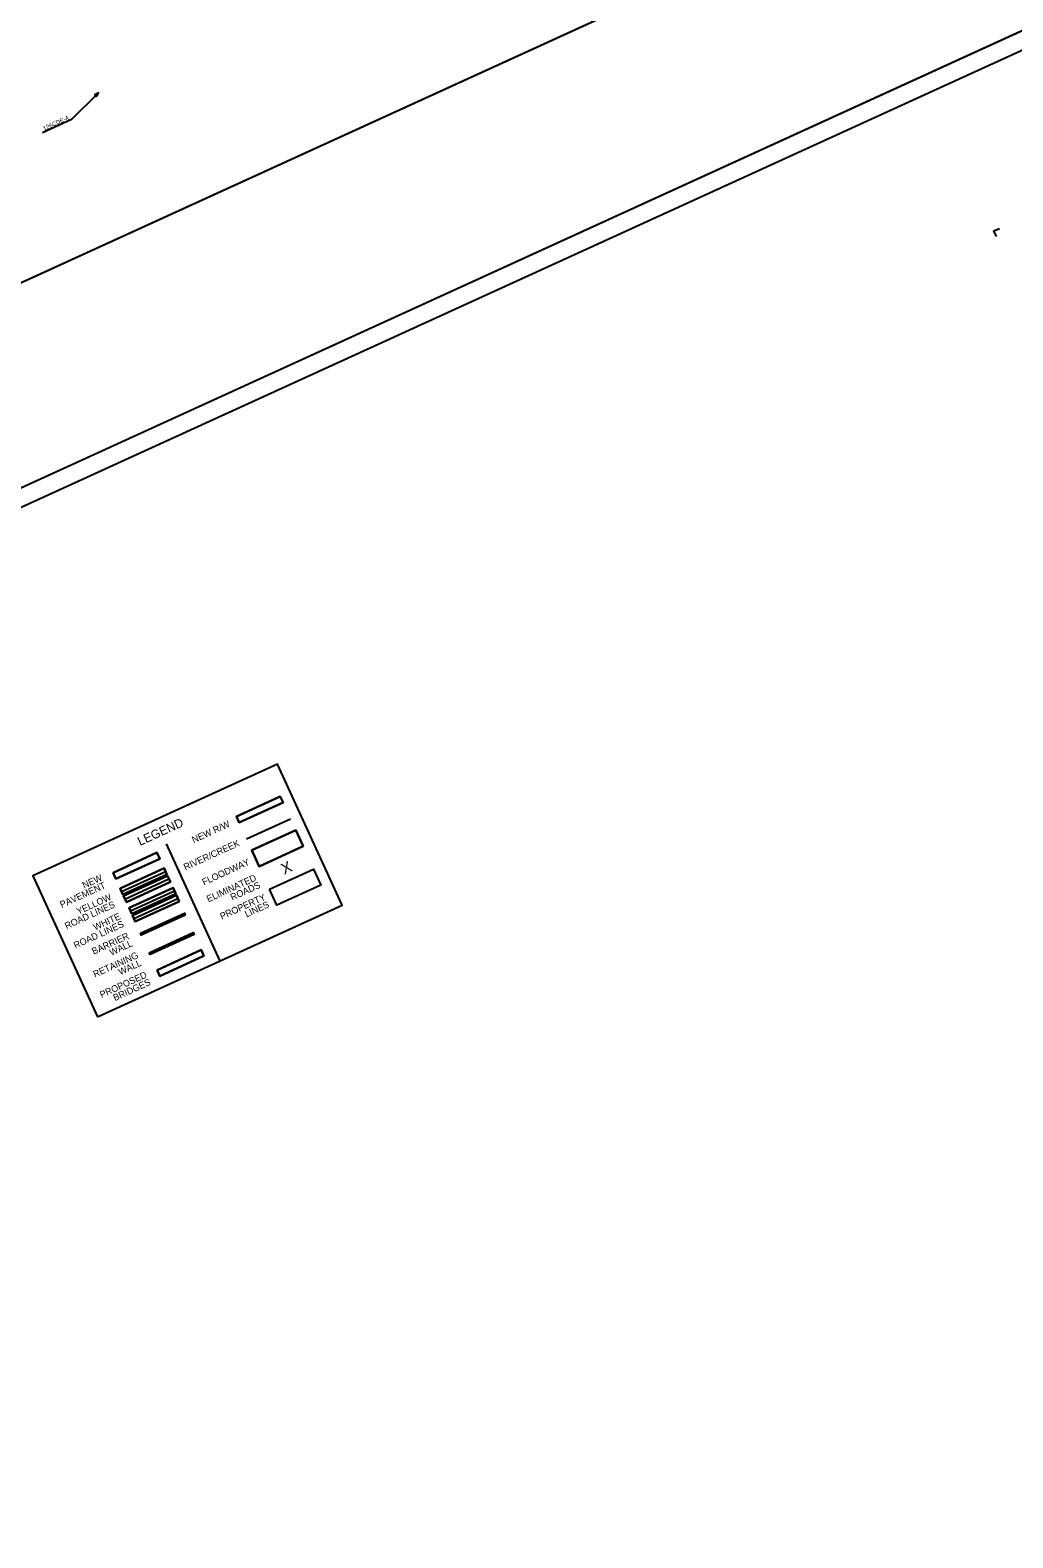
# Model space of a CAD drawing. Extents: x 1952253 to 1982336, y 791177 to 808695.
# Drawn here: x 1967995 to 1973525, y 791177 to 799664 of the extents above; entities that cross this region are included whole.
import ezdxf

# ---------------------------------------------------------------- set-up
doc = ezdxf.new("R2010")
doc.units = 0
for name, color, linetype in [('RD_EX_DV_Prop', 7, 'Continuous'), ('RD_PD_ALT1_CL', 7, 'Continuous'), ('RD_PD_Bridge', 7, 'Continuous'), ('RD_PD_Final_LnLine', 7, 'Continuous'), ('RD_PD_Final_TrvlWay', 7, 'Continuous'), ('RD_PD_MedBWall', 7, 'Continuous'), ('RD_PD_RW', 7, 'Continuous'), ('RD_PD_WallFill', 7, 'Continuous'), ('RD_QTY_Bridge', 7, 'Continuous'), ('RD_QTY_Surf_Course', 7, 'Continuous'), ('RD_SHT_Bndy', 7, 'Continuous'), ('RD_SHT_IplotShp', 7, 'Continuous'), ('RD_SHT_Misc2', 7, 'Continuous'), ('RD_SHT_Misc3', 7, 'Continuous'), ('RD_SHT_ShtClip', 7, 'Continuous'), ('RD_SHT_TX', 7, 'Continuous'), ('RD_Sketch1', 7, 'Continuous'), ('RD_TX_RoadID', 7, 'Continuous')]:
    doc.layers.add(name, color=color, linetype=linetype)

msp = doc.modelspace()

# ---------------------------------------------------------------- linework, layer by layer
at = {"layer": 'RD_EX_DV_Prop'}
msp.add_lwpolyline([(1969342.1, 794828.4), (1969589.7, 794941.5), (1969631.2, 794850.5), (1969383.6, 794737.4)], close=True, dxfattribs=at)
at = {"layer": 'RD_PD_ALT1_CL'}
for p, q in [((1968509.1, 794815.3), (1968756.7, 794928.3)), ((1968528.6, 794772.6), (1968776.2, 794885.7))]:
    msp.add_line(p, q, dxfattribs=at)
at = {"layer": 'RD_PD_Bridge'}
msp.add_lwpolyline([(1968709.6, 794372.9), (1968957.2, 794486), (1968972.8, 794451.9), (1968725.2, 794338.8)], close=True, dxfattribs=at)
at = {"layer": 'RD_PD_Final_LnLine'}
msp.add_line((1968578.6, 794663.2), (1968826.1, 794776.3), dxfattribs=at)
at = {"layer": 'RD_PD_Final_TrvlWay'}
msp.add_line((1968559.1, 794705.9), (1968806.6, 794819), dxfattribs=at)
at = {"layer": 'RD_PD_MedBWall'}
msp.add_lwpolyline([(1968615.2, 794579.7), (1968862.7, 794692.8), (1968867.4, 794682.6), (1968619.8, 794569.5)], close=True, dxfattribs=at)
at = {"layer": 'RD_PD_RW'}
msp.add_lwpolyline([(1969155.2, 795237.5), (1969402.8, 795350.5), (1969418.4, 795316.4), (1969170.8, 795203.3)], close=True, dxfattribs=at)
msp.add_lwpolyline([(1969170.8, 795203.3), (1969418.4, 795316.4), (1969402.8, 795350.5), (1969155.2, 795237.5), (1969170.8, 795203.3)], dxfattribs=at)
at = {"layer": 'RD_PD_WallFill'}
msp.add_lwpolyline([(1968665.1, 794470.3), (1968912.7, 794583.4), (1968917.4, 794573.2), (1968669.8, 794460.1)], close=True, dxfattribs=at)
at = {"layer": 'RD_QTY_Bridge'}
msp.add_lwpolyline([(1968725.2, 794338.8), (1968972.8, 794451.9), (1968957.2, 794486), (1968709.6, 794372.9), (1968725.2, 794338.8)], dxfattribs=at)
at = {"layer": 'RD_QTY_Surf_Course'}
for points in [[(1968461.1, 794920.4), (1968708.7, 795033.5), (1968724.2, 794999.4), (1968476.7, 794886.3)], [(1968501.3, 794832.3), (1968748.9, 794945.4), (1968764.5, 794911.3), (1968516.9, 794798.2)], [(1968520.8, 794789.7), (1968768.4, 794902.8), (1968783.9, 794868.7), (1968536.4, 794755.6)], [(1968551.3, 794722.9), (1968798.9, 794836), (1968814.4, 794801.9), (1968566.9, 794688.8)], [(1968570.8, 794680.3), (1968818.3, 794793.4), (1968833.9, 794759.3), (1968586.3, 794646.2)]]:
    msp.add_lwpolyline(points, close=True, dxfattribs=at)
for points in [[(1968476.7, 794886.3), (1968724.2, 794999.4), (1968708.7, 795033.5), (1968461.1, 794920.4), (1968476.7, 794886.3)], [(1968516.9, 794798.2), (1968764.5, 794911.3), (1968748.9, 794945.4), (1968501.3, 794832.3), (1968516.9, 794798.2)], [(1968536.4, 794755.6), (1968783.9, 794868.7), (1968768.4, 794902.8), (1968520.8, 794789.7), (1968536.4, 794755.6)], [(1968566.9, 794688.8), (1968814.4, 794801.9), (1968798.9, 794836), (1968551.3, 794722.9), (1968566.9, 794688.8)], [(1968586.3, 794646.2), (1968833.9, 794759.3), (1968818.3, 794793.4), (1968570.8, 794680.3), (1968586.3, 794646.2)]]:
    msp.add_lwpolyline(points, dxfattribs=at)
at = {"layer": 'RD_SHT_Bndy'}
msp.add_line((1968760, 795083.9), (1969061.8, 794423.3), dxfattribs=at)
for points in [[(1979125.3, 802195.5), (1955294.1, 791309), (1952385.5, 797676.1), (1976216.7, 808562.6)], [(1959270.9, 793125.7), (1973897.5, 799807.4), (1973461.2, 800762.4), (1958834.7, 794080.8)], [(1968373.5, 794108.9), (1969750.1, 794737.8), (1969387.3, 795532), (1968010.6, 794903.1)]]:
    msp.add_lwpolyline(points, close=True, dxfattribs=at)
at = {"layer": 'RD_SHT_IplotShp'}
msp.add_lwpolyline([(1979257.8, 802146.1), (1955244.7, 791176.5), (1952253, 797725.5), (1976266.1, 808695.1)], close=True, dxfattribs=at)
at = {"layer": 'RD_SHT_Misc2'}
msp.add_lwpolyline([(1973433, 798502.3), (1973418.9, 798533), (1973449.6, 798547)], dxfattribs=at)
at = {"layer": 'RD_SHT_ShtClip'}
msp.add_lwpolyline([(1978689, 803150.6), (1954857.8, 792264.1), (1952385.5, 797676.1), (1976216.7, 808562.6)], close=True, dxfattribs=at)
msp.add_lwpolyline([(1978689, 803150.6), (1954857.8, 792264.1), (1952385.5, 797676.1), (1976216.7, 808562.6)], close=True, dxfattribs=at)
msp.add_lwpolyline([(1978689, 803150.6), (1954857.8, 792264.1), (1952385.5, 797676.1), (1976216.7, 808562.6)], close=True, dxfattribs=at)
msp.add_lwpolyline([(1978689, 803150.6), (1954857.8, 792264.1), (1952385.5, 797676.1), (1976216.7, 808562.6)], close=True, dxfattribs=at)
at = {"layer": 'RD_Sketch1'}
msp.add_line((1969213, 795111), (1969460.5, 795224.1), dxfattribs=at)
msp.add_lwpolyline([(1969242.2, 795047.1), (1969489.7, 795160.2), (1969531.3, 795069.3), (1969283.7, 794956.2)], close=True, dxfattribs=at)
msp.add_lwpolyline([(1969283.7, 794956.2), (1969531.3, 795069.3), (1969489.7, 795160.2), (1969242.2, 795047.1), (1969283.7, 794956.2)], dxfattribs=at)
at = {"layer": 'RD_TX_RoadID'}
msp.add_line((1968227.6, 799160), (1968063.7, 799085.2), dxfattribs=at)
msp.add_lwpolyline([(1968227.6, 799160), (1968378.9, 799310.9)], dxfattribs=at)
msp.add_lwpolyline([(1968366.9, 799290.1), (1968378.9, 799310.9), (1968358.1, 799298.9)], close=True, dxfattribs=at)

# ---------------------------------------------------------------- texts
at = {"layer": 'RD_SHT_Misc3'}
msp.add_text('X', height=62.5, rotation=24.55175, dxfattribs=at).set_placement((1969425, 794909.1))
at = {"layer": 'RD_SHT_TX'}
for s, height, p in [('LEGEND', 50, (1968612.9, 795071)), ('NEW R/W ', 37.5, (1968915.2, 795086.6)), ('RIVER/CREEK', 37.5, (1968868.8, 794933.2)), ('FLOODWAY', 37.5, (1968972.8, 794848.5)), ('NEW', 37.5, (1968298.6, 794830.7)), ('ELIMINATED', 37.5, (1968998.2, 794753.7)), ('PAVEMENT', 37.5, (1968172.6, 794721.6)), ('ROADS', 37.5, (1969132.3, 794763.4)), ('ROAD LINES', 37.5, (1968200.1, 794601.9)), ('YELLOW', 37.5, (1968266.1, 794683.6)), ('PROPERTY ', 37.5, (1969073.3, 794655.8)), ('LINES', 37.5, (1969213.1, 794668.1)), ('ROAD LINES', 37.5, (1968250, 794492.5)), ('WHITE', 37.5, (1968360.6, 794594.6)), ('BARRIER', 37.5, (1968352.7, 794458.8)), ('RETAINING', 37.5, (1968359.5, 794329.7)), ('WALL', 37.5, (1968451.9, 794452.6)), ('WALL', 37.5, (1968501.9, 794343.2)), ('PROPOSED', 37.5, (1968397.2, 794214.7)), ('BRIDGES', 37.5, (1968472, 794197.4))]:
    msp.add_text(s, height=height, rotation=24.55175, dxfattribs=at).set_placement(p)
at = {"layer": 'RD_TX_RoadID'}
msp.add_text('126CDE-4', height=24, rotation=24.55175, dxfattribs=at).set_placement((1968073.6, 799097.4))

doc.saveas('drawing.dxf')
